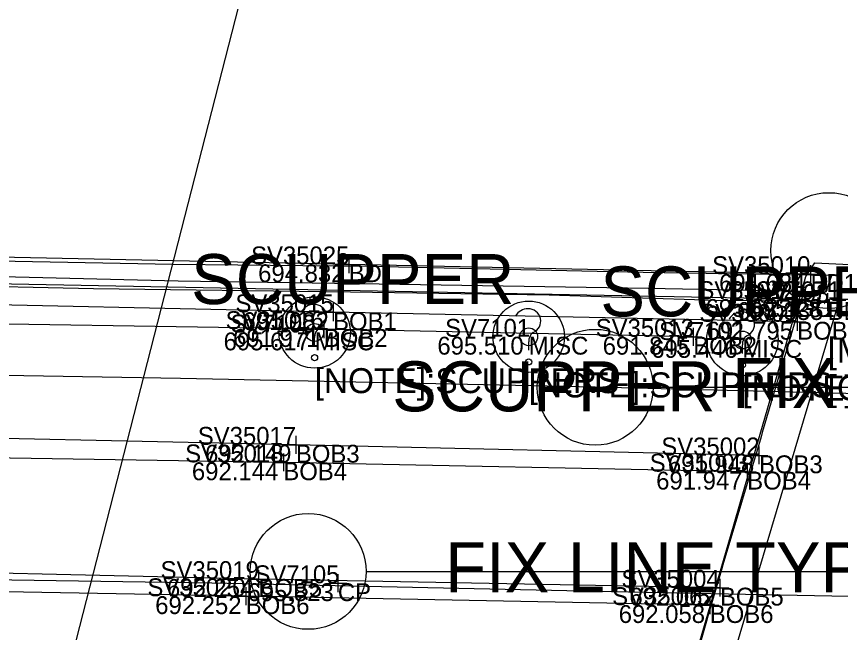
# Model space of a CAD drawing. Extents: x 1659932 to 1663108, y 619867 to 620611.
# Drawn here: x 1661479.69 to 1661525.83, y 620226.44 to 620260.95 of the extents above; entities that cross this region are included whole.
import ezdxf

# ---------------------------------------------------------------- set-up
doc = ezdxf.new("R2010")
doc.units = 0
for name, color, linetype in [('BR_X_Rail_Object', 7, 'Continuous'), ('BR_X_SV_Abut', 7, 'Continuous'), ('BR_X_SV_Bottom_of_Beam', 7, 'Continuous'), ('BR_X_SV_Bottom_of_Beam_Text', 7, 'Continuous'), ('BR_X_SV_Deck_Top', 7, 'Continuous'), ('BR_X_SV_Deck_Top_Text', 7, 'Continuous'), ('PM_X_CL_Double_Solid', 7, 'Continuous'), ('PM_X_Edge_Line', 7, 'Continuous'), ('PV_X_Curb', 7, 'Continuous'), ('RD_X_Concrete_Pad', 7, 'Continuous'), ('RD_X_Misc_Items', 7, 'Continuous'), ('RD_X_Text', 7, 'Continuous'), ('SC_Scratch6', 7, 'Continuous'), ('SV_X_Break_Lines', 7, 'Continuous'), ('SV_X_Shot_Marker', 7, 'Continuous'), ('SV_X_Text', 7, 'Continuous'), ('SV_X_Text_Comment', 7, 'Continuous'), ('SV_X_Text_Elevation', 7, 'Continuous'), ('SV_X_Text_Name', 7, 'Continuous'), ('SV_X_Toe_of_Slope', 7, 'Continuous')]:
    doc.layers.add(name, color=color, linetype=linetype)

msp = doc.modelspace()

# ---------------------------------------------------------------- linework, layer by layer
at = {"layer": 'BR_X_Rail_Object'}
for points in [[(1661525.019, 620245.587), (1661525.344, 620246.45), (1661514.776, 620246.614), (1661499.365, 620246.938), (1661488.433, 620247.052), (1661474.68, 620247.326), (1661456.593, 620247.691), (1661443.635, 620247.905)], [(1661443.687, 620247.108), (1661456.879, 620246.848), (1661474.312, 620246.501), (1661488.734, 620246.14), (1661499.992, 620245.974), (1661515.06, 620245.725), (1661524.66, 620245.538)]]:
    msp.add_lwpolyline(points, dxfattribs=at)
at = {"layer": 'BR_X_SV_Abut'}
msp.add_lwpolyline([(1661523.782, 620245.548), (1661521.437, 620237.652), (1661521.38, 620237.412), (1661519.237, 620230.239), (1661519.158, 620229.96), (1661518.402, 620227.366), (1661518.318, 620227.072), (1661517.057, 620222.643), (1661516.991, 620222.429), (1661516.471, 620219.763), (1661516.177, 620219.661), (1661513.803, 620211.222)], dxfattribs=at)
at = {"layer": 'BR_X_SV_Bottom_of_Beam'}
for points in [[(1661523.404, 620243.849), (1661497.415, 620244.383), (1661471.694, 620244.95), (1661445.773, 620245.45), (1661419.903, 620245.974), (1661394.009, 620246.51), (1661368.147, 620247.032), (1661342.287, 620247.488), (1661316.311, 620248.045), (1661290.557, 620248.602), (1661264.648, 620249.031), (1661238.6, 620249.579)], [(1661517.582, 620243.008), (1661496.897, 620243.44), (1661470.919, 620243.838), (1661445.09, 620244.441), (1661419.147, 620244.946), (1661393.26, 620245.417), (1661367.358, 620245.921), (1661341.629, 620246.518), (1661315.646, 620247.115), (1661289.746, 620247.518), (1661264.383, 620248.322), (1661238.204, 620248.614)], [(1661521.265, 620236.365), (1661495.332, 620236.959), (1661469.491, 620237.512), (1661443.572, 620237.996), (1661417.708, 620238.508), (1661391.884, 620239.08), (1661365.994, 620239.561), (1661340.119, 620240.034), (1661314.197, 620240.589), (1661288.354, 620241.145), (1661262.476, 620241.611), (1661236.623, 620242.15)], [(1661520.605, 620235.452), (1661494.63, 620235.975), (1661468.71, 620236.383), (1661442.944, 620236.996), (1661417.103, 620237.514), (1661391.103, 620237.982), (1661365.202, 620238.448), (1661339.374, 620239.07), (1661313.502, 620239.591), (1661287.59, 620239.99), (1661261.723, 620240.632), (1661235.908, 620241.144)], [(1661519.081, 620228.953), (1661493.234, 620229.438), (1661467.368, 620230.031), (1661441.422, 620230.57), (1661415.6, 620231.071), (1661389.731, 620231.651), (1661363.823, 620232.132), (1661337.817, 620232.613), (1661311.988, 620233.076), (1661286.183, 620233.721), (1661260.328, 620234.129), (1661234.382, 620234.656)], [(1661518.51, 620227.977), (1661492.527, 620228.475), (1661466.56, 620228.954), (1661440.742, 620229.56), (1661414.823, 620230.069), (1661388.938, 620230.522), (1661363.07, 620231.021), (1661337.298, 620231.612), (1661311.527, 620232.162), (1661285.446, 620232.587), (1661259.588, 620233.138), (1661233.669, 620233.674)]]:
    msp.add_lwpolyline(points, dxfattribs=at)
at = {"layer": 'BR_X_SV_Deck_Top'}
msp.add_lwpolyline([(1661524.154, 620246.519), (1661498.291, 620247.067), (1661472.426, 620247.598), (1661446.524, 620248.074), (1661420.55, 620248.604), (1661394.772, 620249.021), (1661368.927, 620249.743), (1661342.743, 620250.117), (1661316.866, 620250.706), (1661291.246, 620251.013), (1661265.132, 620251.796)], dxfattribs=at)
at = {"layer": 'PM_X_CL_Double_Solid'}
msp.add_lwpolyline([(1661546.991, 620228.003), (1661534.02, 620228.314), (1661515.703, 620228.672), (1661490.63, 620229.199), (1661465.719, 620229.574), (1661443.889, 620229.917), (1661424.27, 620230.219), (1661405.796, 620230.53), (1661384.669, 620230.881), (1661362.569, 620231.272), (1661341.508, 620231.739), (1661317.992, 620232.235), (1661293.686, 620232.891), (1661270.168, 620233.351), (1661246.396, 620233.829), (1661221.676, 620234.257), (1661205.714, 620234.618)], dxfattribs=at)
at = {"layer": 'PM_X_Edge_Line'}
msp.add_lwpolyline([(1661550.118, 620239.201), (1661538.667, 620239.519), (1661512.091, 620240.179), (1661488.878, 620240.663), (1661465.84, 620241.071), (1661441.891, 620241.445), (1661414.819, 620241.887), (1661388.375, 620242.338), (1661361.281, 620242.854), (1661333.713, 620243.371), (1661302.167, 620244.004), (1661273.353, 620244.591), (1661246.421, 620245.132), (1661216.402, 620245.664), (1661208.501, 620245.807)], dxfattribs=at)
at = {"layer": 'PV_X_Curb'}
msp.add_lwpolyline([(1661523.342, 620245.121), (1661471.566, 620246.113), (1661445.996, 620246.597), (1661316.22, 620249.01), (1661290.79, 620249.439), (1661264.952, 620250.247), (1661238.714, 620250.79)], dxfattribs=at)
at = {"layer": 'RD_X_Concrete_Pad'}
msp.add_lwpolyline([(1661551.786, 620244.408), (1661525.769, 620245.111), (1661515.918, 620212.007), (1661542.622, 620211.759)], close=True, dxfattribs=at)
at = {"layer": 'RD_X_Misc_Items'}
for p, q in [((1661496.381, 620242.495), (1661496.381, 620242.97)), ((1661508.369, 620242.255), (1661508.369, 620242.73)), ((1661520.336, 620242.075), (1661520.336, 620242.55))]:
    msp.add_line(p, q, dxfattribs=at)
for centre, radius in [((1661496.381, 620243.25), 2), ((1661508.369, 620243.01), 2), ((1661520.336, 620242.83), 2), ((1661496.381, 620243.25), 0.5), ((1661496.381, 620243.25), 0.5), ((1661508.369, 620243.01), 0.5), ((1661508.369, 620243.01), 0.5), ((1661520.336, 620242.83), 0.5), ((1661520.336, 620242.83), 0.5), ((1661496.381, 620241.838), 0.17), ((1661508.369, 620241.598), 0.17), ((1661520.336, 620241.418), 0.17)]:
    msp.add_circle(centre, radius, dxfattribs=at)
for centre, radius, start, end in [((1661496.317, 620244.061), 0.754, 88.324, 152.5385), ((1661496.369, 620244.128), 0.688, 291.9329, 92.4584), ((1661508.305, 620243.821), 0.754, 88.324, 152.5385), ((1661508.357, 620243.888), 0.688, 291.9329, 92.4584), ((1661520.272, 620243.641), 0.754, 88.324, 152.5385), ((1661520.324, 620243.708), 0.688, 291.9329, 92.4584), ((1661496.967, 620243.012), 0.587, 125.4618, 184.0829), ((1661508.955, 620242.772), 0.587, 125.4618, 184.0829), ((1661520.922, 620242.592), 0.587, 125.4618, 184.0829)]:
    msp.add_arc(centre, radius, start, end, dxfattribs=at)
at = {"layer": 'SC_Scratch6'}
for p, q in [((1661515.336, 620240.179), (1661548.139, 620240.179)), ((1661499.267, 620229.865), (1661532.07, 620229.865))]:
    msp.add_line(p, q, dxfattribs=at)
for centre in [(1661525.179, 620247.836), (1661512.091, 620240.179), (1661496.022, 620229.865)]:
    msp.add_circle(centre, 3.245, dxfattribs=at)
at = {"layer": 'SV_X_Break_Lines'}
for points in [[(1661238.016, 620250.735), (1661242.286, 620250.672), (1661247.517, 620250.551), (1661257.182, 620250.394), (1661265.859, 620250.202), (1661279.254, 620249.879), (1661300.715, 620249.466), (1661326.88, 620248.933), (1661355.543, 620248.374), (1661388.796, 620247.704), (1661434.33, 620246.78), (1661467.071, 620246.096), (1661484, 620245.717), (1661498.395, 620245.527), (1661509.52, 620245.356), (1661518.819, 620245.069), (1661524.432, 620245.01)], [(1661523.887, 620246.392), (1661524.393, 620247.156), (1661526.741, 620247.048), (1661530.954, 620246.952), (1661535.021, 620246.785), (1661539.519, 620246.546), (1661540.259, 620246.416), (1661540.238, 620245.201)], [(1661513.46, 620210.943), (1661515.433, 620217.103), (1661516.114, 620219.841), (1661517.694, 620225.043), (1661519.67, 620231.823), (1661520.681, 620235.317), (1661521.758, 620239.035), (1661522.407, 620241.298), (1661523.021, 620243.437), (1661523.887, 620246.392)]]:
    msp.add_lwpolyline(points, dxfattribs=at)
at = {"layer": 'SV_X_Shot_Marker'}
for p, q in [((1661498.291, 620247.567), (1661498.291, 620246.567)), ((1661497.791, 620247.067), (1661498.791, 620247.067)), ((1661498.291, 620247.067), (1661498.291, 620247.067)), ((1661524.154, 620247.019), (1661524.154, 620246.019)), ((1661523.654, 620246.519), (1661524.654, 620246.519)), ((1661524.154, 620246.519), (1661524.154, 620246.519)), ((1661523.342, 620245.621), (1661523.342, 620244.621)), ((1661525.109, 620245.45), (1661525.109, 620244.45)), ((1661525.769, 620245.611), (1661525.769, 620244.611)), ((1661522.842, 620245.121), (1661523.842, 620245.121)), ((1661523.342, 620245.121), (1661523.342, 620245.121)), ((1661525.269, 620245.111), (1661526.269, 620245.111)), ((1661525.769, 620245.111), (1661525.769, 620245.111)), ((1661497.415, 620244.883), (1661497.415, 620243.883)), ((1661524.609, 620244.95), (1661525.609, 620244.95)), ((1661525.109, 620244.95), (1661525.109, 620244.95)), ((1661496.915, 620244.383), (1661497.915, 620244.383)), ((1661497.415, 620244.383), (1661497.415, 620244.383)), ((1661523.404, 620244.349), (1661523.404, 620243.349)), ((1661496.897, 620243.94), (1661496.897, 620242.94)), ((1661522.904, 620243.849), (1661523.904, 620243.849)), ((1661523.404, 620243.849), (1661523.404, 620243.849)), ((1661496.397, 620243.44), (1661497.397, 620243.44)), ((1661496.897, 620243.44), (1661496.897, 620243.44)), ((1661517.582, 620243.508), (1661517.582, 620242.508)), ((1661517.082, 620243.008), (1661518.082, 620243.008)), ((1661517.582, 620243.008), (1661517.582, 620243.008)), ((1661495.332, 620237.459), (1661495.332, 620236.459)), ((1661494.832, 620236.959), (1661495.832, 620236.959)), ((1661495.332, 620236.959), (1661495.332, 620236.959)), ((1661521.265, 620236.865), (1661521.265, 620235.865)), ((1661494.63, 620236.475), (1661494.63, 620235.475)), ((1661520.765, 620236.365), (1661521.765, 620236.365)), ((1661521.265, 620236.365), (1661521.265, 620236.365)), ((1661494.13, 620235.975), (1661495.13, 620235.975)), ((1661494.63, 620235.975), (1661494.63, 620235.975)), ((1661520.605, 620235.952), (1661520.605, 620234.952)), ((1661520.105, 620235.452), (1661521.105, 620235.452)), ((1661520.605, 620235.452), (1661520.605, 620235.452)), ((1661493.234, 620229.938), (1661493.234, 620228.938)), ((1661492.734, 620229.438), (1661493.734, 620229.438)), ((1661493.234, 620229.438), (1661493.234, 620229.438)), ((1661497.682, 620229.703), (1661497.682, 620228.703)), ((1661519.081, 620229.453), (1661519.081, 620228.453)), ((1661492.527, 620228.975), (1661492.527, 620227.975)), ((1661497.182, 620229.203), (1661498.182, 620229.203)), ((1661497.682, 620229.203), (1661497.682, 620229.203)), ((1661518.581, 620228.953), (1661519.581, 620228.953)), ((1661519.081, 620228.953), (1661519.081, 620228.953)), ((1661492.027, 620228.475), (1661493.027, 620228.475)), ((1661492.527, 620228.475), (1661492.527, 620228.475)), ((1661518.51, 620228.477), (1661518.51, 620227.477)), ((1661518.01, 620227.977), (1661519.01, 620227.977)), ((1661518.51, 620227.977), (1661518.51, 620227.977))]:
    msp.add_line(p, q, dxfattribs=at)
at = {"layer": 'SV_X_Toe_of_Slope'}
msp.add_lwpolyline([(1661490.605, 620170.614), (1661477.149, 620203.096), (1661498.786, 620287.484), (1661510.242, 620298.378), (1661539.687, 620302.32)], dxfattribs=at)

# ---------------------------------------------------------------- texts
at = {"layer": 'BR_X_SV_Bottom_of_Beam_Text'}
for s, p in [('SV35015', (1661491.948, 620244.383)), ('SV35001', (1661517.926, 620243.849)), ('SV35016', (1661491.397, 620243.44)), ('691.982', (1661492.342, 620243.383)), ('BOB1', (1661497.415, 620243.383)), ('SV35013', (1661512.122, 620243.008)), ('691.795', (1661518.334, 620242.849)), ('BOB1', (1661523.404, 620242.849)), ('691.971', (1661491.815, 620242.44)), ('BOB2', (1661496.897, 620242.44)), ('691.845', (1661512.512, 620242.008)), ('BOB2', (1661517.582, 620242.008)), ('SV35017', (1661489.84, 620236.959)), ('SV35002', (1661515.796, 620236.365)), ('SV35018', (1661489.133, 620235.975)), ('692.149', (1661490.248, 620235.959)), ('BOB3', (1661495.332, 620235.959)), ('SV35003', (1661515.145, 620235.452)), ('691.948', (1661516.165, 620235.365)), ('BOB3', (1661521.265, 620235.365)), ('692.144', (1661489.508, 620234.975)), ('BOB4', (1661494.63, 620234.975)), ('691.947', (1661515.509, 620234.452)), ('BOB4', (1661520.605, 620234.452)), ('SV35019', (1661487.754, 620229.438)), ('SV35004', (1661513.563, 620228.953)), ('SV35020', (1661487.017, 620228.475)), ('692.254', (1661488.112, 620228.438)), ('BOB5', (1661493.234, 620228.438)), ('SV35005', (1661513.043, 620227.977)), ('692.062', (1661514.008, 620227.953)), ('BOB5', (1661519.081, 620227.953)), ('692.252', (1661487.454, 620227.475)), ('BOB6', (1661492.527, 620227.475)), ('692.058', (1661513.41, 620226.977)), ('BOB6', (1661518.51, 620226.977))]:
    msp.add_text(s, height=1, dxfattribs=at).set_placement(p)
at = {"layer": 'BR_X_SV_Deck_Top_Text'}
for s, p in [('SV35025', (1661492.824, 620247.067)), ('SV35010', (1661518.644, 620246.519)), ('694.832', (1661493.218, 620246.067)), ('BD1', (1661498.291, 620246.067)), ('694.684', (1661519.032, 620245.519)), ('BD1', (1661524.154, 620245.519)), ('SV7103', (1661520.447, 620244.95)), ('695.335', (1661520.039, 620243.95)), ('BD', (1661525.109, 620243.95))]:
    msp.add_text(s, height=1, dxfattribs=at).set_placement(p)
at = {"layer": 'RD_X_Text'}
for p in [(1661489.466, 620244.84), (1661512.382, 620244.15), (1661500.724, 620238.831)]:
    msp.add_text('SCUPPER', height=2.8, dxfattribs=at).set_placement(p)
at = {"layer": 'SC_Scratch6'}
for p in [(1661519.765, 620239.012), (1661503.696, 620228.698)]:
    msp.add_text('FIX LINE TYPES', height=2.79999, dxfattribs=at).set_placement(p)
at = {"layer": 'SV_X_Text'}
for s, p in [('[MATERIAL]:Concrete', (1661525.109, 620241.55)), ('[NOTE]:SCUPPERS', (1661496.381, 620239.85)), ('[NOTE]:SCUPPERS', (1661508.369, 620239.61)), ('[NOTE]:SCUPPERS', (1661520.336, 620239.43)), ('[CONDITION]:Fair', (1661525.109, 620239.45))]:
    msp.add_text(s, height=1.4, dxfattribs=at).set_placement(p)
at = {"layer": 'SV_X_Text_Comment'}
for s, p in [('GUT1', (1661523.342, 620244.121)), ('MISC', (1661496.381, 620242.25)), ('MISC', (1661508.369, 620242.01)), ('MISC', (1661520.336, 620241.83)), ('CP', (1661497.682, 620228.203))]:
    msp.add_text(s, height=1, dxfattribs=at).set_placement(p)
at = {"layer": 'SV_X_Text_Elevation'}
for s, p in [('695.622', (1661518.269, 620244.121)), ('695.281', (1661520.687, 620244.111)), ('695.617', (1661491.285, 620242.25)), ('695.510', (1661503.255, 620242.01)), ('695.446', (1661515.232, 620241.83)), ('695.823', (1661492.618, 620228.203))]:
    msp.add_text(s, height=1, dxfattribs=at).set_placement(p)
at = {"layer": 'SV_X_Text_Name'}
for s, p in [('SV35012', (1661517.873, 620245.121)), ('SV7071', (1661521.089, 620245.111)), ('SV7100', (1661491.669, 620243.25)), ('SV7101', (1661503.689, 620243.01)), ('SV7102', (1661515.665, 620242.83)), ('SV7105', (1661493.013, 620229.203))]:
    msp.add_text(s, height=1, dxfattribs=at).set_placement(p)

doc.saveas('drawing.dxf')
